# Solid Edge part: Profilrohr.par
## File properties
Username: bmolnar
Dokumentum tartalom típus: 0
Author: bmolnar
Last saved by: bmolnar
Revision: 83
Sűrűség: 0,000 kg/m^3
Pontosság: 0,990
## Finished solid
Body 1: solid body, 115 faces, 338 edges, 224 vertices.
  Faces by surface: cylinder 59, plane 56
  Edges by curve: line 220, circle 118
Bounding box of the edges (mm): 95.500 x 95.500 x 74.000, from (-47.75, -47.75, -45) to (47.75, 47.75, 29).
Cylindrical faces by radius (mm): R0.2 x24, R0.5 x24, R1 x4, R10 x4, R13.5 x2, R40 x1
Planar faces by outward normal: +x 13, +y 14, +z 1, -x 13, -y 14, -z 1
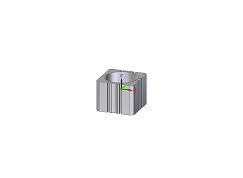
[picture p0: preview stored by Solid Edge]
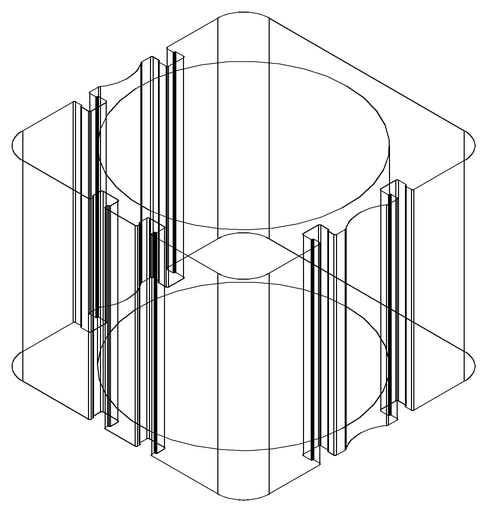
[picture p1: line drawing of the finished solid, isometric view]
